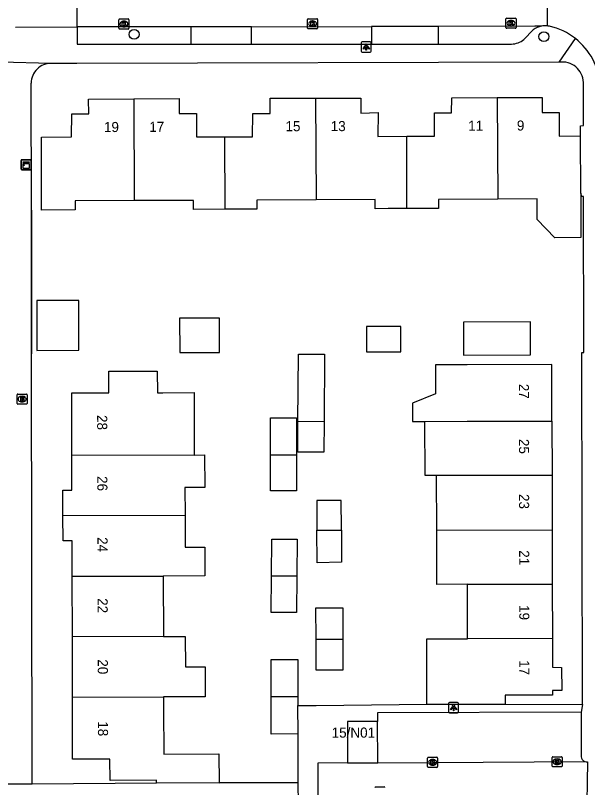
# Model space of a CAD drawing. Extents: x 160457 to 162082, y 388340 to 389736.
# Drawn here: x 160888.5 to 160945.3, y 388547.2 to 388623.8 of the extents above; entities that cross this region are included whole.
import ezdxf

# ---------------------------------------------------------------- set-up
doc = ezdxf.new("R2010")
doc.units = 0
for name, color, linetype in [('IMGEO_Boom', 7, 'Continuous'), ('IMGEO_Brandkraan', 7, 'Continuous'), ('IMGEO_Kast', 7, 'Continuous'), ('IMGEO_Kolk', 7, 'Continuous'), ('IMGEO_Lichtpunt', 7, 'Continuous'), ('IMGEO_Muur', 7, 'Continuous'), ('IMGEO_Pand', 7, 'Continuous'), ('IMGEO_Pand_nummerreeks', 7, 'Continuous'), ('IMGEO_Parkeervlak_open', 7, 'Continuous'), ('IMGEO_Rijbaan_lokaal_open', 7, 'Continuous'), ('IMGEO_Rioolput', 7, 'Continuous'), ('IMGEO_Voetpad_open', 7, 'Continuous')]:
    doc.layers.add(name, color=color, linetype=linetype)

msp = doc.modelspace()

# ---------------------------------------------------------------- linework, layer by layer
at = {"layer": 'IMGEO_Boom'}
for centre in [(160900.313, 388621.931), (160940.984, 388621.708)]:
    msp.add_circle(centre, 0.489, dxfattribs=at)
at = {"layer": 'IMGEO_Brandkraan'}
for p, q in [((160888.695, 388585.298), (160888.695, 388586.15)), ((160888.77, 388586.224), (160889.622, 388586.224)), ((160889.696, 388586.15), (160889.696, 388585.298)), ((160889.206, 388585.444), (160889.181, 388585.444)), ((160889.183, 388586.004), (160889.208, 388586.004)), ((160889.622, 388585.224), (160888.77, 388585.224))]:
    msp.add_line(p, q, dxfattribs=at)
for points in [[(160888.695, 388585.298), (160888.695, 388586.15)], [(160888.77, 388586.224), (160889.622, 388586.224)], [(160889.696, 388586.15), (160889.696, 388585.298)], [(160889.043, 388585.924), (160889.043, 388585.524), (160889.256, 388585.524)], [(160889.274, 388585.924), (160889.043, 388585.924)], [(160889.222, 388585.843), (160889.168, 388585.843), (160889.168, 388585.767)], [(160889.168, 388585.767), (160889.221, 388585.767)], [(160889.23, 388585.691), (160889.168, 388585.691), (160889.168, 388585.61)], [(160889.168, 388585.61), (160889.23, 388585.61)], [(160889.622, 388585.224), (160888.77, 388585.224)]]:
    msp.add_lwpolyline(points, dxfattribs=at)
for centre, radius, start, end in [((160888.772, 388586.148), 0.0765, 91.55205, 178.44795), ((160888.772, 388586.148), 0.0765, 91.55205, 178.44795), ((160889.62, 388586.148), 0.0765, 1.55205, 88.44795), ((160889.62, 388586.148), 0.0765, 1.55205, 88.44795), ((160888.772, 388585.3), 0.0765, 181.55205, 268.44795), ((160888.772, 388585.3), 0.0765, 181.55205, 268.44795), ((160889.223, 388585.805), 0.0379, 267.82845, 90.93552), ((160889.231, 388585.65), 0.0404, 269.87594, 90.50774), ((160889.262, 388585.775), 0.251, 268.66757, 293.53466), ((160889.278, 388585.779), 0.145, 59.4692, 91.53667), ((160889.303, 388585.826), 0.0922, 285.51372, 58.15012), ((160889.308, 388585.634), 0.105, 301.31148, 78.98903), ((160889.62, 388585.3), 0.0765, 271.55205, 358.44795), ((160889.62, 388585.3), 0.0765, 271.55205, 358.44795)]:
    msp.add_arc(centre, radius, start, end, dxfattribs=at)
for centre, major_axis, ratio, start_param, end_param in [((160889.182, 388585.724), (-0.387, 0.002), 0.722429, 4.712389, 7.853982), ((160889.207, 388585.724), (-0.39, 0.002), 0.717154, 1.570796, 4.712389)]:
    msp.add_ellipse(centre, major_axis=major_axis, ratio=ratio, start_param=start_param, end_param=end_param, dxfattribs=at)
at = {"layer": 'IMGEO_Kast'}
for p, q in [((160889.092, 388608.565), (160889.092, 388609.406)), ((160889.092, 388609.406), (160889.092, 388608.565)), ((160889.167, 388609.49), (160890.008, 388609.49)), ((160890.008, 388609.49), (160889.167, 388609.49)), ((160890.092, 388609.415), (160890.092, 388608.574)), ((160890.092, 388608.574), (160890.092, 388609.415)), ((160890.017, 388608.49), (160889.176, 388608.49)), ((160889.176, 388608.49), (160890.017, 388608.49))]:
    msp.add_line(p, q, dxfattribs=at)
for points in [[(160889.287, 388609.28), (160889.887, 388609.28), (160889.887, 388609.195), (160889.287, 388609.195), (160889.287, 388609.28)], [(160889.287, 388609.105), (160889.887, 388609.105), (160889.887, 388608.616), (160889.287, 388608.616), (160889.287, 388609.105)]]:
    msp.add_lwpolyline(points, dxfattribs=at)
msp.add_circle((160889.371, 388608.954), 0.0377, dxfattribs=at)
for centre, start, end in [((160889.17, 388609.412), 92.4484, 184.28452), ((160889.17, 388609.412), 92.4484, 184.28452), ((160890.014, 388609.412), 2.4484, 94.28452), ((160890.014, 388609.412), 2.4484, 94.28452), ((160889.17, 388608.568), 182.4484, 274.28452), ((160889.17, 388608.568), 182.4484, 274.28452), ((160890.014, 388608.568), 272.4484, 4.28452), ((160890.014, 388608.568), 272.4484, 4.28452)]:
    msp.add_arc(centre, 0.0779, start, end, dxfattribs=at)
at = {"layer": 'IMGEO_Kolk'}
for p, q in [((160898.797, 388622.533), (160898.797, 388623.385)), ((160898.872, 388623.459), (160899.724, 388623.459)), ((160899.285, 388623.239), (160899.31, 388623.239)), ((160899.798, 388623.385), (160899.798, 388622.533)), ((160917.528, 388622.558), (160917.528, 388623.41)), ((160917.603, 388623.484), (160918.455, 388623.484)), ((160918.016, 388623.264), (160918.041, 388623.264)), ((160918.529, 388623.41), (160918.529, 388622.558)), ((160937.222, 388622.611), (160937.222, 388623.463)), ((160937.297, 388623.537), (160938.149, 388623.537)), ((160937.71, 388623.317), (160937.735, 388623.317)), ((160938.223, 388623.463), (160938.223, 388622.611)), ((160899.724, 388622.459), (160898.872, 388622.459)), ((160899.308, 388622.679), (160899.283, 388622.679)), ((160918.455, 388622.484), (160917.603, 388622.484)), ((160918.039, 388622.704), (160918.014, 388622.704)), ((160938.149, 388622.537), (160937.297, 388622.537)), ((160937.733, 388622.757), (160937.708, 388622.757)), ((160929.44, 388549.232), (160929.44, 388550.084)), ((160929.515, 388550.158), (160930.367, 388550.158)), ((160930.441, 388550.084), (160930.441, 388549.232)), ((160941.804, 388549.292), (160941.804, 388550.144)), ((160941.879, 388550.218), (160942.731, 388550.218)), ((160942.292, 388549.998), (160942.317, 388549.998)), ((160942.805, 388550.144), (160942.805, 388549.292)), ((160929.951, 388549.378), (160929.926, 388549.378)), ((160929.928, 388549.938), (160929.953, 388549.938)), ((160942.731, 388549.218), (160941.879, 388549.218)), ((160942.315, 388549.438), (160942.29, 388549.438)), ((160930.367, 388549.158), (160929.515, 388549.158))]:
    msp.add_line(p, q, dxfattribs=at)
for points in [[(160898.797, 388622.533), (160898.797, 388623.385)], [(160898.872, 388623.459), (160899.724, 388623.459)], [(160899.118, 388623.159), (160899.241, 388623.159), (160899.241, 388623.008), (160899.371, 388623.159), (160899.535, 388623.159), (160899.389, 388623.008), (160899.542, 388622.759), (160899.39, 388622.759), (160899.305, 388622.923), (160899.241, 388622.856), (160899.241, 388622.759), (160899.118, 388622.759), (160899.118, 388623.159)], [(160899.798, 388623.385), (160899.798, 388622.533)], [(160917.528, 388622.558), (160917.528, 388623.41)], [(160917.603, 388623.484), (160918.455, 388623.484)], [(160917.849, 388623.184), (160917.972, 388623.184), (160917.972, 388623.033), (160918.102, 388623.184), (160918.266, 388623.184), (160918.12, 388623.033), (160918.273, 388622.784), (160918.121, 388622.784), (160918.036, 388622.948), (160917.972, 388622.881), (160917.972, 388622.784), (160917.849, 388622.784), (160917.849, 388623.184)], [(160918.529, 388623.41), (160918.529, 388622.558)], [(160937.222, 388622.611), (160937.222, 388623.463)], [(160937.297, 388623.537), (160938.149, 388623.537)], [(160937.543, 388623.237), (160937.666, 388623.237), (160937.666, 388623.086), (160937.796, 388623.237), (160937.96, 388623.237), (160937.814, 388623.086), (160937.967, 388622.837), (160937.815, 388622.837), (160937.73, 388623.001), (160937.666, 388622.934), (160937.666, 388622.837), (160937.543, 388622.837), (160937.543, 388623.237)], [(160938.223, 388623.463), (160938.223, 388622.611)], [(160899.724, 388622.459), (160898.872, 388622.459)], [(160918.455, 388622.484), (160917.603, 388622.484)], [(160938.149, 388622.537), (160937.297, 388622.537)], [(160929.44, 388549.232), (160929.44, 388550.084)], [(160929.515, 388550.158), (160930.367, 388550.158)], [(160930.441, 388550.084), (160930.441, 388549.232)], [(160941.804, 388549.292), (160941.804, 388550.144)], [(160941.879, 388550.218), (160942.731, 388550.218)], [(160942.805, 388550.144), (160942.805, 388549.292)], [(160929.761, 388549.858), (160929.884, 388549.858), (160929.884, 388549.707), (160930.014, 388549.858), (160930.178, 388549.858), (160930.032, 388549.707), (160930.185, 388549.458), (160930.033, 388549.458), (160929.948, 388549.622), (160929.884, 388549.555), (160929.884, 388549.458), (160929.761, 388549.458), (160929.761, 388549.858)], [(160942.731, 388549.218), (160941.879, 388549.218)], [(160942.125, 388549.918), (160942.248, 388549.918), (160942.248, 388549.767), (160942.378, 388549.918), (160942.542, 388549.918), (160942.396, 388549.767), (160942.549, 388549.518), (160942.397, 388549.518), (160942.312, 388549.682), (160942.248, 388549.615), (160942.248, 388549.518), (160942.125, 388549.518), (160942.125, 388549.918)], [(160930.367, 388549.158), (160929.515, 388549.158)]]:
    msp.add_lwpolyline(points, dxfattribs=at)
for centre, start, end in [((160898.874, 388623.383), 91.55205, 178.44795), ((160898.874, 388623.383), 91.55205, 178.44795), ((160899.722, 388623.383), 1.55205, 88.44795), ((160899.722, 388623.383), 1.55205, 88.44795), ((160917.605, 388623.408), 91.55205, 178.44795), ((160917.605, 388623.408), 91.55205, 178.44795), ((160918.453, 388623.408), 1.55205, 88.44795), ((160918.453, 388623.408), 1.55205, 88.44795), ((160937.299, 388623.461), 91.55205, 178.44795), ((160937.299, 388623.461), 91.55205, 178.44795), ((160938.147, 388623.461), 1.55205, 88.44795), ((160938.147, 388623.461), 1.55205, 88.44795), ((160898.874, 388622.535), 181.55205, 268.44795), ((160898.874, 388622.535), 181.55205, 268.44795), ((160899.722, 388622.535), 271.55205, 358.44795), ((160899.722, 388622.535), 271.55205, 358.44795), ((160917.605, 388622.56), 181.55205, 268.44795), ((160917.605, 388622.56), 181.55205, 268.44795), ((160918.453, 388622.56), 271.55205, 358.44795), ((160918.453, 388622.56), 271.55205, 358.44795), ((160937.299, 388622.613), 181.55205, 268.44795), ((160937.299, 388622.613), 181.55205, 268.44795), ((160938.147, 388622.613), 271.55205, 358.44795), ((160938.147, 388622.613), 271.55205, 358.44795), ((160929.517, 388550.082), 91.55205, 178.44795), ((160929.517, 388550.082), 91.55205, 178.44795), ((160930.365, 388550.082), 1.55205, 88.44795), ((160930.365, 388550.082), 1.55205, 88.44795), ((160941.881, 388550.142), 91.55205, 178.44795), ((160941.881, 388550.142), 91.55205, 178.44795), ((160942.729, 388550.142), 1.55205, 88.44795), ((160942.729, 388550.142), 1.55205, 88.44795), ((160929.517, 388549.234), 181.55205, 268.44795), ((160929.517, 388549.234), 181.55205, 268.44795), ((160930.365, 388549.234), 271.55205, 358.44795), ((160930.365, 388549.234), 271.55205, 358.44795), ((160941.881, 388549.294), 181.55205, 268.44795), ((160941.881, 388549.294), 181.55205, 268.44795), ((160942.729, 388549.294), 271.55205, 358.44795), ((160942.729, 388549.294), 271.55205, 358.44795)]:
    msp.add_arc(centre, 0.0765, start, end, dxfattribs=at)
for centre, major_axis, ratio, start_param, end_param in [((160899.284, 388622.959), (-0.387, 0.002), 0.722429, 4.712389, 7.853982), ((160899.309, 388622.959), (-0.39, 0.002), 0.717154, 1.570796, 4.712389), ((160918.015, 388622.984), (-0.387, 0.002), 0.722429, 4.712389, 7.853982), ((160918.04, 388622.984), (-0.39, 0.002), 0.717154, 1.570796, 4.712389), ((160937.709, 388623.037), (-0.387, 0.002), 0.722429, 4.712389, 7.853982), ((160937.734, 388623.037), (-0.39, 0.002), 0.717154, 1.570796, 4.712389), ((160942.291, 388549.718), (-0.387, 0.002), 0.722429, 4.712389, 7.853982), ((160942.316, 388549.718), (-0.39, 0.002), 0.717154, 1.570796, 4.712389), ((160929.927, 388549.658), (-0.387, 0.002), 0.722429, 4.712389, 7.853982), ((160929.952, 388549.658), (-0.39, 0.002), 0.717154, 1.570796, 4.712389)]:
    msp.add_ellipse(centre, major_axis=major_axis, ratio=ratio, start_param=start_param, end_param=end_param, dxfattribs=at)
at = {"layer": 'IMGEO_Lichtpunt'}
for p, q in [((160922.849, 388621.082), (160922.849, 388620.275)), ((160922.849, 388621.082), (160922.849, 388620.275)), ((160923.751, 388621.177), (160922.943, 388621.177)), ((160923.751, 388621.177), (160922.943, 388621.177)), ((160923.845, 388620.275), (160923.845, 388621.082)), ((160923.845, 388620.275), (160923.845, 388621.082)), ((160922.943, 388620.181), (160923.751, 388620.181)), ((160922.943, 388620.181), (160923.751, 388620.181)), ((160931.525, 388555.491), (160931.525, 388554.684)), ((160931.525, 388555.491), (160931.525, 388554.684)), ((160932.427, 388555.586), (160931.619, 388555.586)), ((160932.427, 388555.586), (160931.619, 388555.586)), ((160932.521, 388554.684), (160932.521, 388555.491)), ((160932.521, 388554.684), (160932.521, 388555.491)), ((160931.619, 388554.59), (160932.427, 388554.59)), ((160931.619, 388554.59), (160932.427, 388554.59))]:
    msp.add_line(p, q, dxfattribs=at)
for points in [[(160923.223, 388620.746), (160923.262, 388620.718), (160923.074, 388620.456), (160923.036, 388620.483), (160923.223, 388620.746)], [(160923.325, 388620.698), (160923.372, 388620.698), (160923.372, 388620.376), (160923.325, 388620.376), (160923.325, 388620.698)], [(160923.435, 388620.718), (160923.473, 388620.745), (160923.66, 388620.483), (160923.621, 388620.455), (160923.435, 388620.718)], [(160931.899, 388555.155), (160931.938, 388555.127), (160931.75, 388554.865), (160931.712, 388554.892), (160931.899, 388555.155)], [(160932.001, 388555.107), (160932.048, 388555.107), (160932.048, 388554.785), (160932.001, 388554.785), (160932.001, 388555.107)], [(160932.111, 388555.127), (160932.149, 388555.154), (160932.336, 388554.892), (160932.297, 388554.864), (160932.111, 388555.127)]]:
    msp.add_lwpolyline(points, dxfattribs=at)
for centre in [(160923.348, 388620.88), (160932.024, 388555.289)]:
    msp.add_circle(centre, 0.0994, dxfattribs=at)
for centre, start, end in [((160922.943, 388621.082), 90, 180), ((160922.943, 388621.082), 90, 180), ((160923.751, 388621.082), 0, 90), ((160923.751, 388621.082), 0, 90), ((160922.943, 388620.275), 180, 270), ((160922.943, 388620.275), 180, 270), ((160923.751, 388620.275), 270, 0), ((160923.751, 388620.275), 270, 360), ((160931.619, 388555.491), 90, 180), ((160931.619, 388555.491), 90, 180), ((160932.427, 388555.491), 0, 90), ((160932.427, 388555.491), 0, 90), ((160931.619, 388554.684), 180, 270), ((160931.619, 388554.684), 180, 270), ((160932.427, 388554.684), 270, 0), ((160932.427, 388554.684), 270, 360)]:
    msp.add_arc(centre, 0.0946, start, end, dxfattribs=at)
at = {"layer": 'IMGEO_Muur'}
for points in [[(160890.112, 388604.489), (160890.136, 388590.2)], [(160918.389, 388555.314), (160929.373, 388555.426)], [(160916.591, 388547.646), (160916.585, 388552.478)], [(160908.741, 388547.618), (160916.591, 388547.646)]]:
    msp.add_lwpolyline(points, dxfattribs=at)
at = {"layer": 'IMGEO_Pand'}
for points in [[(160900.328, 388605.429), (160894.449, 388605.406), (160894.452, 388604.506), (160891.122, 388604.493), (160891.102, 388611.722), (160894.103, 388611.743), (160894.112, 388614.038), (160895.811, 388614.047), (160895.792, 388615.504), (160900.288, 388615.533)], [(160900.288, 388615.533), (160904.787, 388615.563), (160904.794, 388614.07), (160906.503, 388614.075), (160906.514, 388611.751), (160909.313, 388611.758)], [(160900.288, 388615.533), (160900.328, 388605.429)], [(160909.313, 388611.758), (160912.064, 388611.765), (160912.112, 388614.081), (160913.831, 388614.077), (160913.82, 388615.592), (160918.328, 388615.6)], [(160918.328, 388615.6), (160922.803, 388615.608), (160922.8, 388614.095), (160924.54, 388614.161), (160924.513, 388611.803), (160927.367, 388611.82)], [(160918.328, 388615.6), (160918.368, 388605.501)], [(160927.367, 388611.82), (160930.12, 388611.837), (160930.127, 388614.132), (160931.83, 388614.136), (160931.842, 388615.637), (160936.362, 388615.655)], [(160936.362, 388615.655), (160940.812, 388615.672), (160940.818, 388614.173), (160942.508, 388614.18), (160942.516, 388611.839), (160944.635, 388611.85)], [(160936.362, 388615.655), (160936.402, 388605.573)], [(160909.341, 388604.565), (160909.313, 388611.758)], [(160927.396, 388604.637), (160927.367, 388611.82)], [(160944.655, 388606.156), (160944.635, 388611.85)], [(160944.655, 388606.156), (160944.671, 388601.751), (160942.072, 388601.742), (160940.315, 388603.537), (160940.308, 388605.589), (160936.402, 388605.573)], [(160909.341, 388604.565), (160906.203, 388604.553), (160906.199, 388605.452), (160900.328, 388605.429)], [(160918.368, 388605.501), (160912.49, 388605.478), (160912.493, 388604.578), (160909.341, 388604.565)], [(160927.396, 388604.637), (160925.536, 388604.63), (160924.245, 388604.625), (160924.241, 388605.524), (160918.368, 388605.501)], [(160936.402, 388605.573), (160930.532, 388605.55), (160930.535, 388604.65), (160927.396, 388604.637)], [(160894.826, 388590.57), (160894.814, 388595.519), (160890.642, 388595.51), (160890.654, 388590.56), (160894.826, 388590.57)], [(160908.797, 388590.354), (160908.785, 388593.756), (160904.821, 388593.742), (160904.833, 388590.34), (160908.797, 388590.354)], [(160926.78, 388590.421), (160926.775, 388592.935), (160923.384, 388592.928), (160923.389, 388590.414), (160926.78, 388590.421)], [(160933.017, 388593.368), (160933.023, 388590.096), (160939.652, 388590.109), (160939.645, 388593.381), (160933.017, 388593.368)], [(160916.575, 388583.48), (160916.616, 388590.185), (160919.201, 388590.17), (160919.16, 388583.485)], [(160941.79, 388583.531), (160941.779, 388589.151), (160933.36, 388589.134), (160930.224, 388589.128), (160930.23, 388586.256), (160927.932, 388585.301), (160927.936, 388583.503), (160929.185, 388583.506)], [(160894.132, 388580.138), (160894.116, 388586.339), (160897.816, 388586.349), (160897.811, 388588.479), (160902.611, 388588.492), (160902.617, 388586.353), (160903.167, 388586.355), (160906.257, 388586.366), (160906.279, 388580.169)], [(160913.845, 388580.188), (160913.845, 388583.848), (160916.438, 388583.848), (160916.438, 388580.195)], [(160919.16, 388583.485), (160919.141, 388580.449), (160916.556, 388580.465), (160916.575, 388583.48)], [(160919.16, 388583.485), (160916.575, 388583.48)], [(160929.185, 388583.506), (160933.371, 388583.514), (160941.79, 388583.531)], [(160930.343, 388578.122), (160929.196, 388578.12), (160929.185, 388583.506)], [(160941.79, 388583.531), (160941.801, 388578.142)], [(160893.249, 388574.124), (160893.242, 388576.682), (160894.141, 388576.684), (160894.132, 388580.138)], [(160906.279, 388580.169), (160894.132, 388580.138)], [(160906.279, 388580.169), (160907.308, 388580.172), (160907.317, 388576.95), (160905.355, 388576.945), (160905.362, 388574.152)], [(160916.438, 388580.195), (160916.438, 388576.63), (160913.845, 388576.63), (160913.845, 388580.188)], [(160913.845, 388580.188), (160916.438, 388580.195)], [(160941.801, 388578.142), (160933.382, 388578.128), (160930.343, 388578.122)], [(160930.354, 388572.718), (160930.343, 388578.122)], [(160941.801, 388578.142), (160941.812, 388572.741)], [(160920.89, 388572.699), (160920.889, 388572.825), (160920.875, 388575.653), (160918.447, 388575.639), (160918.464, 388572.694)], [(160905.362, 388574.152), (160893.249, 388574.124)], [(160894.163, 388568.127), (160894.154, 388571.664), (160893.255, 388571.662), (160893.249, 388574.124)], [(160905.362, 388574.152), (160905.37, 388571.015), (160907.332, 388571.02), (160907.339, 388568.162), (160903.208, 388568.151)], [(160920.89, 388572.699), (160920.906, 388569.517), (160918.482, 388569.458), (160918.464, 388572.694)], [(160918.464, 388572.694), (160920.89, 388572.699)], [(160930.354, 388572.718), (160941.812, 388572.741)], [(160933.405, 388567.334), (160930.365, 388567.328), (160930.354, 388572.718)], [(160941.812, 388572.741), (160941.823, 388567.351)], [(160913.954, 388568.18), (160913.978, 388571.824), (160916.488, 388571.808), (160916.464, 388568.186)], [(160894.163, 388568.127), (160903.208, 388568.151)], [(160894.179, 388562.126), (160894.163, 388568.127)], [(160903.208, 388568.151), (160903.221, 388562.147)], [(160916.464, 388568.186), (160916.44, 388564.535), (160913.93, 388564.551), (160913.954, 388568.18)], [(160913.954, 388568.18), (160916.464, 388568.186)], [(160933.405, 388567.334), (160941.823, 388567.351)], [(160933.416, 388561.924), (160933.405, 388567.334)], [(160941.823, 388567.351), (160941.834, 388561.941)], [(160918.369, 388561.894), (160918.359, 388565.004), (160921.019, 388565.012), (160921.029, 388561.899)], [(160903.221, 388562.147), (160894.179, 388562.126)], [(160894.194, 388556.126), (160894.179, 388562.126)], [(160903.221, 388562.147), (160905.391, 388562.152), (160905.398, 388559.144), (160907.36, 388559.149), (160907.367, 388556.155), (160903.234, 388556.146)], [(160921.029, 388561.899), (160921.038, 388558.813), (160918.378, 388558.805), (160918.369, 388561.894)], [(160918.369, 388561.894), (160921.029, 388561.899)], [(160929.373, 388555.426), (160929.367, 388561.916), (160933.416, 388561.924)], [(160941.834, 388561.941), (160933.416, 388561.924)], [(160941.834, 388561.941), (160941.84, 388559.091), (160942.721, 388559.088), (160942.756, 388556.793), (160941.851, 388556.779), (160941.839, 388556.336), (160937.15, 388556.333), (160937.152, 388555.434)], [(160913.917, 388556.17), (160913.907, 388559.87), (160916.567, 388559.877), (160916.576, 388556.176)], [(160894.194, 388556.126), (160903.234, 388556.146)], [(160902.52, 388547.596), (160902.519, 388547.884), (160897.919, 388547.869), (160897.9, 388549.968), (160894.21, 388549.964), (160894.194, 388556.126)], [(160903.234, 388556.146), (160903.237, 388554.987), (160903.247, 388550.469), (160908.731, 388550.488), (160908.741, 388547.618)], [(160916.576, 388556.176), (160913.917, 388556.17)], [(160916.585, 388552.478), (160913.926, 388552.472), (160913.917, 388556.17)], [(160916.576, 388556.176), (160916.578, 388555.308)], [(160929.373, 388555.426), (160937.152, 388555.434)], [(160916.585, 388552.478), (160916.578, 388555.308)], [(160924.47, 388553.705), (160921.477, 388553.704), (160921.503, 388549.594)], [(160924.49, 388549.612), (160924.47, 388553.705)], [(160921.503, 388549.594), (160924.49, 388549.612)], [(160908.741, 388547.618), (160902.52, 388547.596)]]:
    msp.add_lwpolyline(points, dxfattribs=at)
at = {"layer": 'IMGEO_Parkeervlak_open'}
for points in [[(160905.936, 388622.685), (160905.939, 388621.191), (160905.94, 388620.969)], [(160911.951, 388620.969), (160911.95, 388621.194), (160911.947, 388622.695)], [(160923.885, 388622.715), (160923.889, 388621.227), (160923.889, 388620.969)], [(160930.529, 388620.969), (160930.524, 388622.726)]]:
    msp.add_lwpolyline(points, dxfattribs=at)
at = {"layer": 'IMGEO_Rijbaan_lokaal_open'}
for points in [[(160894.662, 388622.666), (160894.661, 388627.437)], [(160941.339, 388627.57), (160941.315, 388623.065), (160941.313, 388622.774)], [(160888.531, 388622.655), (160894.662, 388622.666)], [(160905.936, 388622.685), (160894.662, 388622.666)], [(160911.947, 388622.695), (160905.936, 388622.685)], [(160911.947, 388622.695), (160923.885, 388622.715)], [(160930.524, 388622.726), (160923.885, 388622.715)], [(160940.749, 388622.743), (160940.085, 388622.742), (160930.524, 388622.726)], [(160921.503, 388549.594), (160918.544, 388549.593), (160918.547, 388543.611), (160921.988, 388543.619)], [(160924.49, 388549.612), (160929.937, 388549.657), (160945.054, 388549.734)], [(160945.054, 388549.734), (160945.194, 388549.713), (160945.317, 388549.695), (160945.204, 388543.676)]]:
    msp.add_lwpolyline(points, dxfattribs=at)
for centre, radius, start, end in [((160941.143, 388620.729), 2.052, 85.23637, 101.05577), ((160941.08, 388620.25), 2.535, 79.58783, 84.72278), ((160940.091, 388616.378), 6.527, 51.78897, 77.18821), ((160940.092, 388616.381), 6.524, 4.885, 51.7793)]:
    msp.add_arc(centre, radius, start, end, dxfattribs=at)
at = {"layer": 'IMGEO_Rioolput'}
msp.add_line((160924.282, 388547.229), (160925.134, 388547.229), dxfattribs=at)
msp.add_lwpolyline([(160924.282, 388547.229), (160925.134, 388547.229)], dxfattribs=at)
for centre, start, end in [((160924.284, 388547.153), 91.55205, 178.44795), ((160924.284, 388547.153), 91.55205, 178.44795), ((160925.132, 388547.153), 1.55205, 88.44795), ((160925.132, 388547.153), 1.55205, 88.44795)]:
    msp.add_arc(centre, 0.0765, start, end, dxfattribs=at)
at = {"layer": 'IMGEO_Voetpad_open'}
for points in [[(160894.662, 388622.666), (160894.665, 388621.166), (160894.665, 388620.969), (160905.685, 388620.969), (160905.94, 388620.969)], [(160938.997, 388621.431), (160939.928, 388622.39)], [(160942.507, 388619.163), (160944.128, 388621.507)], [(160905.94, 388620.969), (160911.951, 388620.969)], [(160911.951, 388620.969), (160912.33, 388620.969), (160923.701, 388620.969), (160923.889, 388620.969)], [(160923.889, 388620.969), (160930.529, 388620.969)], [(160930.529, 388620.969), (160937.784, 388620.974)], [(160892.082, 388619.048), (160887.065, 388619.167)], [(160942.507, 388619.163), (160894.635, 388619.052), (160892.082, 388619.048)], [(160890.205, 388547.5), (160890.136, 388590.2), (160890.112, 388604.489), (160890.091, 388617.099)], [(160944.635, 388611.85), (160944.632, 388612.867), (160944.915, 388612.872), (160944.907, 388617.16)], [(160944.828, 388555.395), (160944.768, 388590.348), (160944.952, 388590.348), (160944.927, 388605.843), (160944.746, 388605.849), (160944.655, 388606.156)], [(160916.578, 388555.308), (160918.389, 388555.314), (160929.373, 388555.426)], [(160937.152, 388555.434), (160944.828, 388555.395)], [(160944.828, 388555.395), (160944.685, 388554.654)], [(160944.685, 388554.654), (160924.48, 388554.587), (160924.47, 388553.705)], [(160944.685, 388554.654), (160944.681, 388550.218)], [(160916.591, 388547.646), (160916.585, 388552.478)], [(160890.205, 388547.5), (160887.189, 388547.484)], [(160902.52, 388547.596), (160890.205, 388547.5)], [(160916.591, 388547.646), (160908.741, 388547.618)], [(160916.616, 388545.542), (160916.591, 388547.646)]]:
    msp.add_lwpolyline(points, dxfattribs=at)
for centre, radius, start, end in [((160941.141, 388620.701), 2.079, 100.85532, 125.67656), ((160937.763, 388622.867), 1.893, 270.62516, 310.66282), ((160892.056, 388617.083), 1.965, 89.2408, 179.53771), ((160942.833, 388617.114), 2.075, 1.27101, 99.03337), ((160945.272, 388550.288), 0.595, 186.72964, 248.51045)]:
    msp.add_arc(centre, radius, start, end, dxfattribs=at)

# ---------------------------------------------------------------- texts
at = {"layer": 'IMGEO_Pand_nummerreeks'}
for s, rotation, p in [('19', 0.23568, (160897.32, 388612.23)), ('17', 0.23568, (160901.817, 388612.249)), ('15', 0.10205, (160915.337, 388612.314)), ('13', 0.10205, (160919.828, 388612.322)), ('11', 0.22356, (160933.477, 388612.364)), ('9', 0.22356, (160938.308, 388612.382)), ('27', 270.10292, (160938.503, 388587.236)), ('28', 270.14806, (160896.642, 388584.137)), ('25', 270.10292, (160938.513, 388581.767)), ('26', 270.14806, (160896.657, 388578.078)), ('23', 270.10476, (160938.522, 388576.298)), ('24', 270.14806, (160896.673, 388572.015)), ('21', 270.10476, (160938.532, 388570.716)), ('22', 270.14806, (160896.689, 388565.956)), ('19', 270.10476, (160938.542, 388565.268)), ('20', 270.14806, (160896.704, 388559.887)), ('17', 270.10476, (160938.552, 388559.799)), ('18', 270.14806, (160896.72, 388553.734))]:
    msp.add_text(s, height=1, rotation=rotation, dxfattribs=at).set_placement(p)
msp.add_text('15/N01', height=1, dxfattribs=at).set_placement((160919.919, 388552.112))

doc.saveas('drawing.dxf')
